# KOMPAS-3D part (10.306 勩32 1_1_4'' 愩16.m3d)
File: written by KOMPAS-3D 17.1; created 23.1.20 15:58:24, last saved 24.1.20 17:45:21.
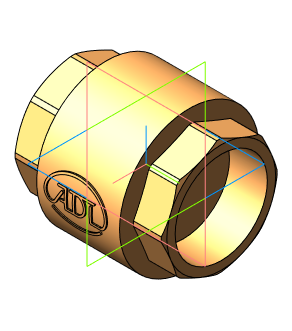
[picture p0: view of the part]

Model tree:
1. Операция без истории:2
